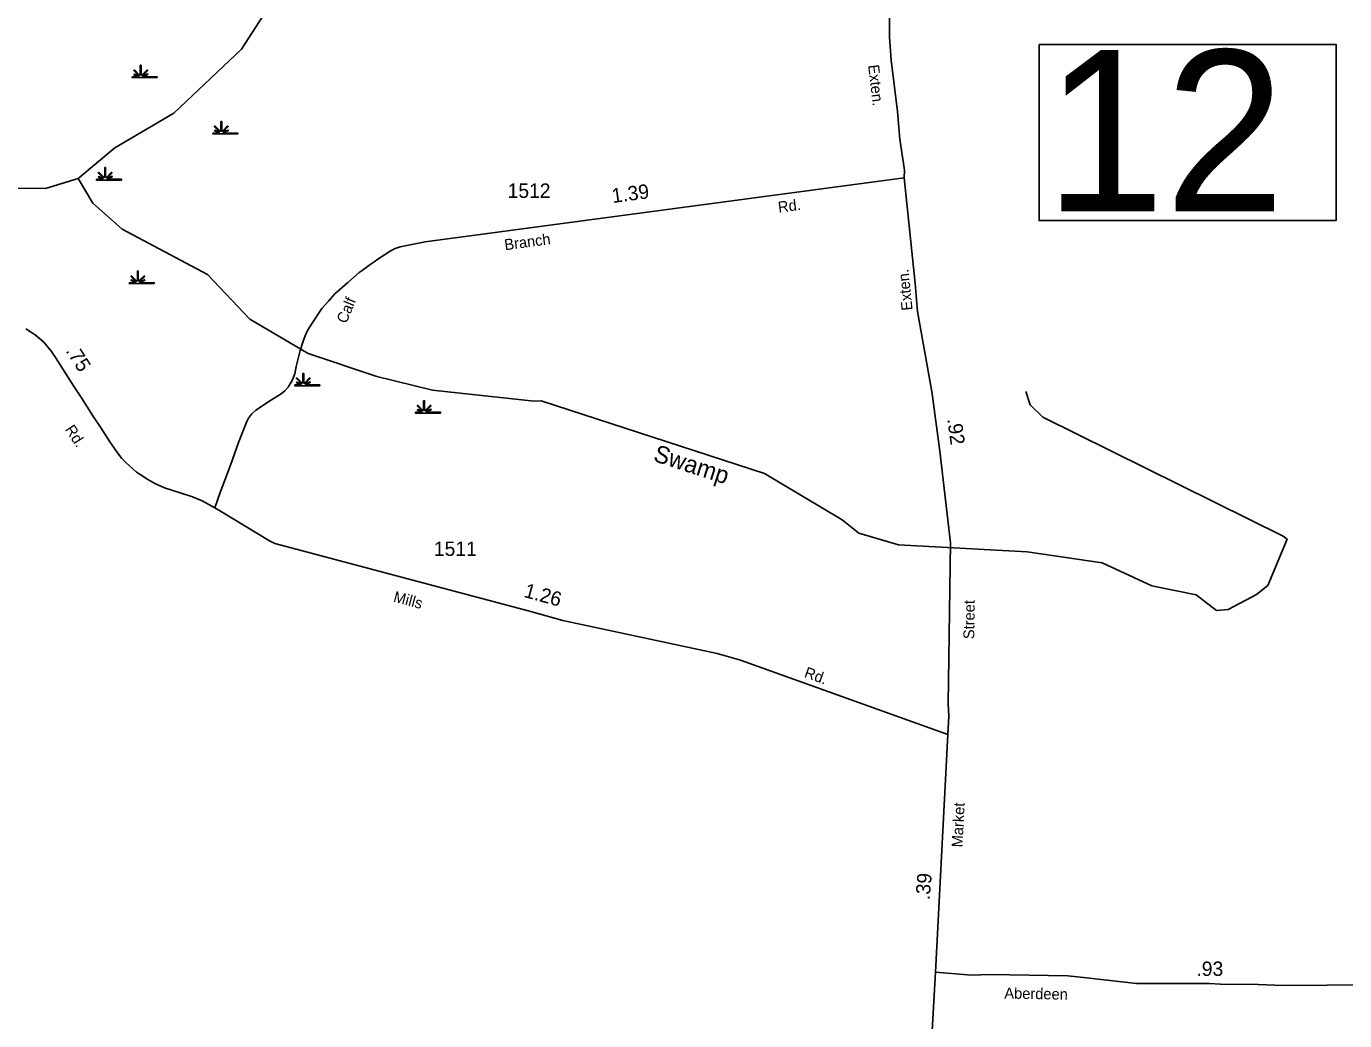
# Model space of a CAD drawing. Extents: x 2532689 to 2764727, y 536648 to 732970.
# Drawn here: x 2577230 to 2588671, y 682821 to 691449 of the extents above; entities that cross this region are included whole.
import ezdxf

# ---------------------------------------------------------------- set-up
doc = ezdxf.new("R2010")
doc.units = 0
for name, color, linetype in [('Exist Hydrographic Creek Single Shore', 7, 'Continuous'), ('Exist Hydrographic Swamp CELL', 7, 'Continuous'), ('Exist Hydrographic Swamp Label', 7, 'Continuous'), ('Exist Road Primary NC Structure Standard Bridge Number Label', 7, 'Continuous'), ('Exist Road Secondary Mileage Hundredths English Label', 7, 'Continuous'), ('Exist Road Secondary Type 51 Attributed', 7, 'Continuous'), ('Exist Road Secondary Type 51 Label', 7, 'Continuous'), ('Exist Road Secondary Type 51 Number Label', 7, 'Continuous')]:
    doc.layers.add(name, color=color, linetype=linetype)

msp = doc.modelspace()

# ---------------------------------------------------------------- linework, layer by layer
at = {"layer": 'Exist Hydrographic Creek Single Shore'}
msp.add_line((2581697, 688199), (2581637, 688198), dxfattribs=at)
for points in [[(2577679, 690129), (2577998, 690395), (2578509, 690695), (2579098, 691251), (2579373, 691679)], [(2577679, 690129), (2577397, 690042), (2577114, 690044), (2576543, 690215), (2576159, 690268), (2575508, 690337), (2575083, 690336), (2574609, 690294), (2574236, 690180), (2574053, 690160)], [(2581637, 688198), (2580756, 688291), (2580271, 688412), (2579675, 688611), (2579169, 688909), (2578803, 689295), (2578062, 689689), (2577808, 689915), (2577679, 690129)], [(2581697, 688199), (2583636, 687570), (2584310, 687168), (2584454, 687052), (2584798, 686951), (2585916, 686888), (2586568, 686793), (2586997, 686593), (2587382, 686517), (2587559, 686380), (2587659, 686390), (2587907, 686519), (2588005, 686598), (2588172, 686999), (2588139, 687024), (2586051, 688059), (2585941, 688166), (2585905, 688281)]]:
    msp.add_lwpolyline(points, dxfattribs=at)
at = {"layer": 'Exist Hydrographic Swamp CELL'}
for points in [[(2578148, 691012), (2578200, 691012), (2578202, 691015), (2578164, 691030), (2578167, 691035), (2578205, 691020), (2578206, 691023), (2578162, 691067), (2578167, 691072), (2578212, 691027), (2578219, 691029), (2578219, 691112), (2578226, 691112), (2578226, 691029), (2578232, 691027), (2578278, 691072), (2578283, 691067), (2578238, 691023), (2578240, 691019), (2578281, 691038), (2578284, 691032), (2578243, 691015), (2578244, 691012), (2578365, 691012), (2578365, 691005), (2578148, 691005)], [(2578847, 690524), (2578900, 690524), (2578902, 690528), (2578863, 690543), (2578866, 690548), (2578904, 690532), (2578906, 690535), (2578861, 690580), (2578866, 690585), (2578912, 690539), (2578918, 690542), (2578918, 690625), (2578925, 690625), (2578925, 690542), (2578931, 690539), (2578977, 690585), (2578982, 690580), (2578937, 690535), (2578939, 690532), (2578980, 690550), (2578983, 690545), (2578942, 690527), (2578943, 690524), (2579064, 690524), (2579064, 690517), (2578847, 690517)], [(2577839, 690123), (2577892, 690123), (2577894, 690127), (2577856, 690142), (2577859, 690147), (2577896, 690131), (2577898, 690134), (2577853, 690178), (2577859, 690184), (2577904, 690138), (2577910, 690141), (2577910, 690224), (2577917, 690224), (2577917, 690141), (2577924, 690138), (2577969, 690184), (2577974, 690178), (2577930, 690134), (2577932, 690130), (2577973, 690149), (2577975, 690144), (2577934, 690126), (2577936, 690123), (2578057, 690123), (2578057, 690116), (2577839, 690116)], [(2578123, 689225), (2578175, 689225), (2578177, 689229), (2578139, 689243), (2578142, 689249), (2578180, 689233), (2578181, 689236), (2578137, 689280), (2578142, 689285), (2578187, 689240), (2578194, 689242), (2578194, 689325), (2578201, 689325), (2578201, 689242), (2578207, 689240), (2578253, 689285), (2578258, 689280), (2578213, 689236), (2578215, 689232), (2578256, 689251), (2578259, 689246), (2578218, 689228), (2578219, 689225), (2578340, 689225), (2578340, 689218), (2578123, 689218)], [(2579559, 688338), (2579611, 688338), (2579613, 688342), (2579575, 688356), (2579578, 688362), (2579616, 688346), (2579617, 688349), (2579573, 688393), (2579578, 688398), (2579623, 688353), (2579630, 688355), (2579630, 688438), (2579637, 688438), (2579637, 688355), (2579643, 688353), (2579688, 688398), (2579694, 688393), (2579649, 688349), (2579651, 688345), (2579692, 688364), (2579694, 688359), (2579653, 688341), (2579655, 688338), (2579776, 688338), (2579776, 688331), (2579559, 688331)], [(2580607, 688100), (2580660, 688101), (2580662, 688104), (2580624, 688119), (2580627, 688124), (2580664, 688108), (2580666, 688111), (2580622, 688156), (2580627, 688161), (2580672, 688115), (2580678, 688118), (2580678, 688201), (2580686, 688201), (2580686, 688118), (2580692, 688115), (2580737, 688161), (2580742, 688156), (2580698, 688111), (2580700, 688108), (2580741, 688126), (2580743, 688121), (2580702, 688103), (2580704, 688101), (2580825, 688100), (2580825, 688093), (2580607, 688093)]]:
    msp.add_lwpolyline(points, close=True, dxfattribs=at)
at = {"layer": 'Exist Road Primary NC Structure Standard Bridge Number Label'}
msp.add_lwpolyline([(2586020, 691293), (2588597, 691293), (2588597, 689764), (2586020, 689764)], close=True, dxfattribs=at)
at = {"layer": 'Exist Road Secondary Type 51 Attributed'}
msp.add_line((2585226, 685303), (2585119, 683243), dxfattribs=at)
for points in [[(2585351, 694124), (2585299, 694017), (2585094, 693473), (2584925, 692991), (2584893, 692901), (2584853, 692718), (2584833, 692569), (2584790, 692445), (2584733, 692169), (2584733, 692087), (2584725, 692007), (2584721, 691357), (2584737, 691155), (2584790, 690712), (2584811, 690471), (2584852, 690202), (2584847, 690136)], [(2578865, 687272), (2578911, 687404), (2578953, 687512), (2579001, 687641), (2579072, 687837), (2579119, 687962), (2579143, 688020), (2579159, 688048), (2579185, 688083), (2579222, 688120), (2579358, 688207), (2579442, 688260), (2579474, 688287), (2579503, 688319), (2579538, 688377), (2579559, 688434), (2579572, 688497), (2579605, 688636), (2579632, 688717), (2579650, 688765), (2579670, 688809), (2579710, 688875), (2579795, 689000), (2579851, 689066), (2579908, 689127), (2580020, 689228), (2580119, 689314), (2580143, 689331), (2580191, 689365), (2580290, 689434), (2580388, 689500), (2580403, 689506), (2580431, 689521), (2580473, 689537), (2580690, 689580), (2584847, 690136)], [(2584847, 690136), (2584943, 689217), (2584964, 688974), (2585090, 688264), (2585091, 688260), (2585158, 687764), (2585250, 686966), (2585231, 685571), (2585237, 685463), (2585226, 685303)], [(2578865, 687272), (2578841, 687287), (2578756, 687331), (2578673, 687367), (2578564, 687401), (2578429, 687444), (2578346, 687482), (2578285, 687516), (2578219, 687559), (2578187, 687582), (2578154, 687609), (2578095, 687663), (2578057, 687703), (2578015, 687757), (2577955, 687844), (2577872, 687972), (2577807, 688070), (2577708, 688226), (2577646, 688322), (2577484, 688575), (2577449, 688627), (2577381, 688709), (2577307, 688772), (2577226, 688826)], [(2585226, 685303), (2583427, 685948), (2583224, 686008), (2581887, 686294), (2581597, 686374), (2579385, 686963), (2579339, 686986), (2578916, 687243), (2578865, 687272)], [(2585119, 683243), (2585087, 682630), (2585041, 681821), (2585045, 681519), (2585247, 680875), (2585812, 679284), (2585884, 679075), (2586338, 677946)], [(2585119, 683243), (2585433, 683215), (2585595, 683222), (2586269, 683209), (2586430, 683192), (2586865, 683143), (2587497, 683143), (2587593, 683137), (2587921, 683136), (2588137, 683126), (2590042, 683139)]]:
    msp.add_lwpolyline(points, dxfattribs=at)

# ---------------------------------------------------------------- texts
at = {"layer": 'Exist Hydrographic Swamp Label'}
msp.add_text('Swamp', height=150, rotation=342.0368, dxfattribs=at).set_placement((2582663, 687680))
at = {"layer": 'Exist Road Primary NC Structure Standard Bridge Number Label'}
msp.add_text('12', height=1400, dxfattribs=at).set_placement((2586070, 689843))
at = {"layer": 'Exist Road Secondary Mileage Hundredths English Label'}
for s, rotation, p in [('1.39', 7.6069, (2582319, 689916)), ('.75', 302.6621, (2577567, 688634)), ('.92', 277.6869, (2585222, 688041)), ('1.26', 344.5183, (2581541, 686499)), ('.39', 84.9559, (2585069, 683865)), ('.93', 0.0303, (2587385, 683209))]:
    msp.add_text(s, height=125, rotation=rotation, dxfattribs=at).set_placement(p)
at = {"layer": 'Exist Road Secondary Type 51 Label'}
for s, rotation, p in [('Exten.', 276.7907, (2584535, 691112)), ('Rd.', 7.6069, (2583760, 689832)), ('Branch', 7.6069, (2581385, 689506)), ('Exten.', 95.9672, (2584922, 688988)), ('Calf', 67.1757, (2580006, 688864)), ('Rd.', 303.4551, (2577561, 687952)), ('Mills', 345.0955, (2580409, 686458)), ('Street', 89.2327, (2585457, 686131)), ('Rd.', 340.2813, (2583974, 685804)), ('Market', 87.0014, (2585354, 684323)), ('Aberdeen', 358.9172, (2585717, 683013))]:
    msp.add_text(s, height=95, rotation=rotation, dxfattribs=at).set_placement(p)
at = {"layer": 'Exist Road Secondary Type 51 Number Label'}
for s, p in [('1512', (2581407, 689961)), ('1511', (2580767, 686854))]:
    msp.add_text(s, height=125, dxfattribs=at).set_placement(p)

doc.saveas('drawing.dxf')
